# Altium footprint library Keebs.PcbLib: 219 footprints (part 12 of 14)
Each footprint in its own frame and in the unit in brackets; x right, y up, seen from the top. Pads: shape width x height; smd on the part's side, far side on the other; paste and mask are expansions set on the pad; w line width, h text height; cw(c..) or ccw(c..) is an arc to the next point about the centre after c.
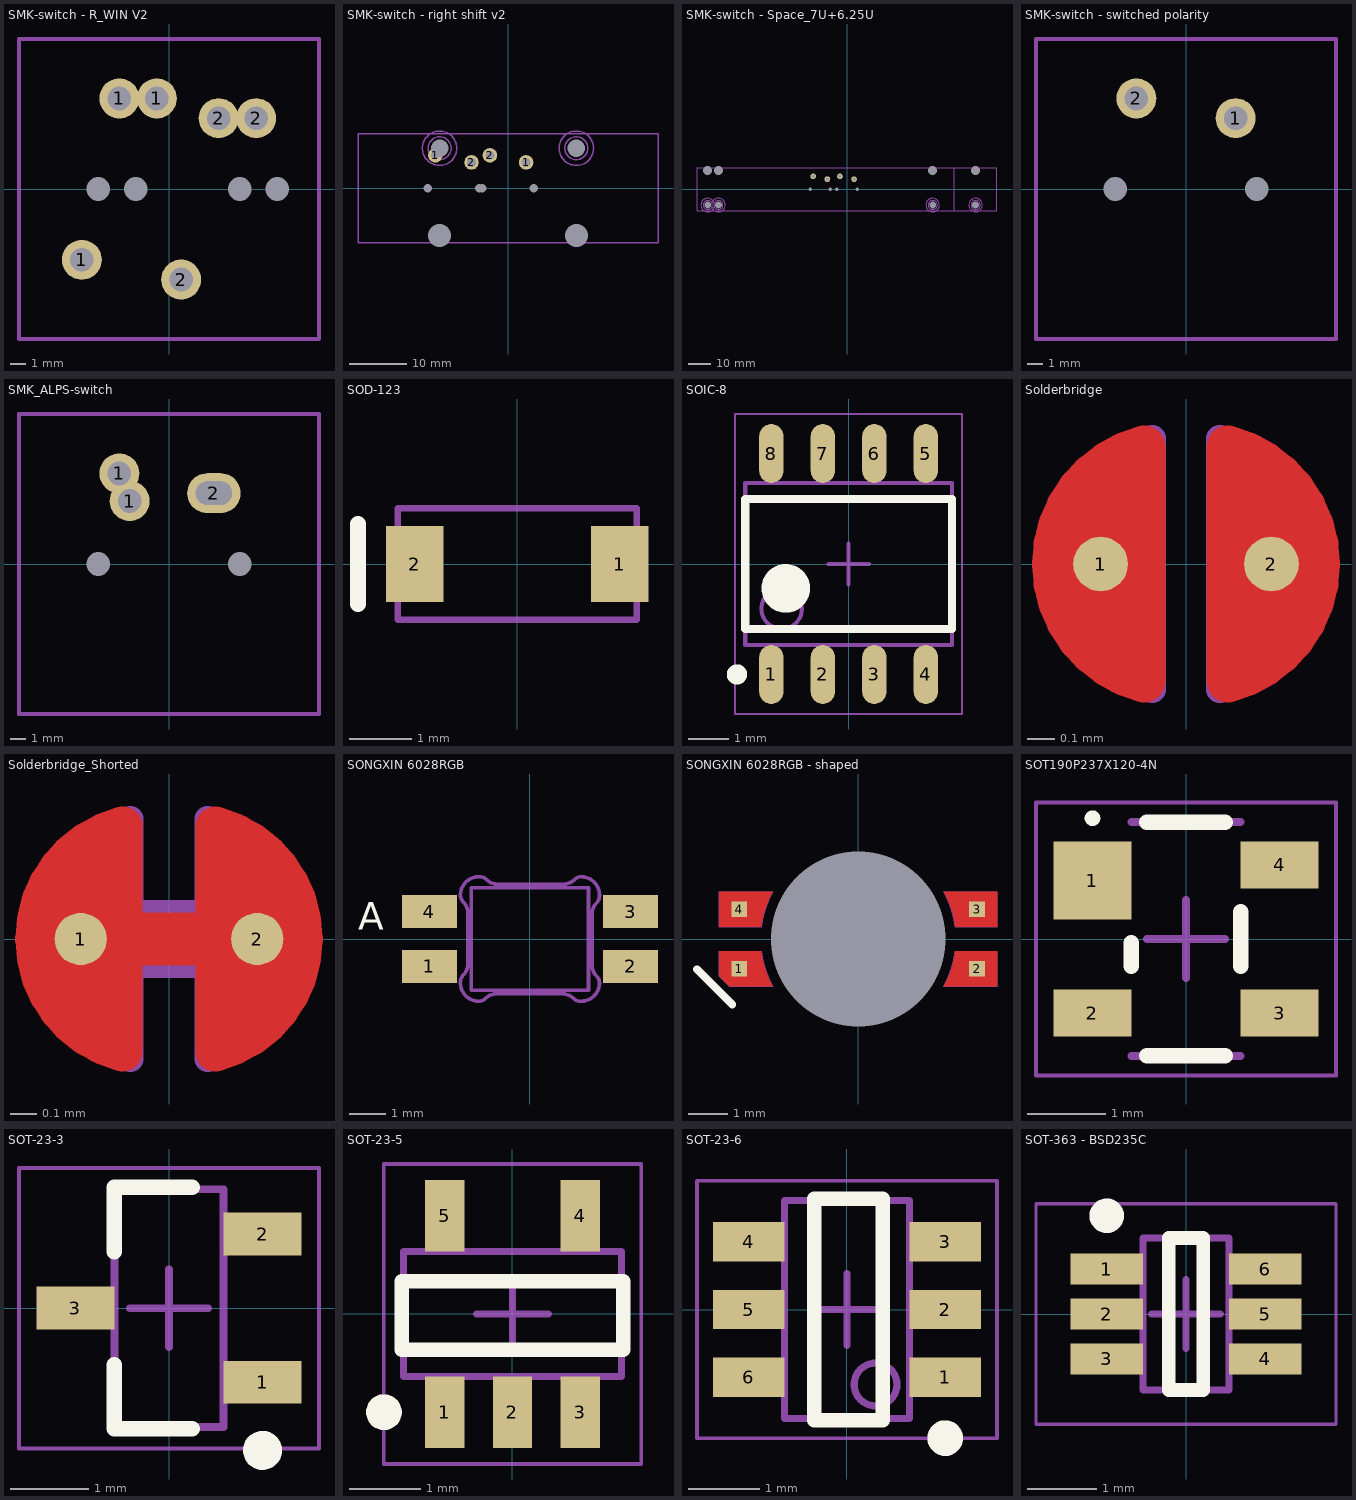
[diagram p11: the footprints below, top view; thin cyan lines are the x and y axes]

## SMK-switch - R_WIN V2 [mm] "Common tsangan and WK bottom + AEK"
pads (13):
  round 2.54 hole 1.5 mask-0.5: 1(-5.531,-4.5) 1(-3.15,5.75) 1(-0.769,5.75) 2(0.769,-5.75) 2(3.15,4.5) 2(5.531,4.5)
  round 1 hole 1.5 unplated: ""(-4.5,0) ""(-2.119,0) ""(4.5,0) ""(6.881,0)
  round 1 on Mech13: ""(-2.381,0) ""(0,0) ""(2.381,0)
Mechanical 13:
  lines w0.254: -9.525,-9.525 -9.525,9.525 9.525,9.525 9.525,-9.525 -9.525,-9.525
  text ".Designator" at -4.225,-8.325 h0.7

## SMK-switch - right shift v2 [mm]
pads (14):
  round 2.54 hole 1.5 mask-0.5: 1(-12.675,5.75) 1(3.15,4.5) 2(-6.375,4.5) 2(-3.15,5.75)
  round 1 hole 1.5 unplated: ""(-14.025,0) ""(-5.025,0) ""(-4.5,0) ""(4.5,0)
  round 1.524 hole 4 unplated: ""(-11.938,-8.255) ""(11.938,-8.255)
  round 1.524 hole 3.048 unplated: ""(-11.938,6.985) ""(11.938,6.985)
  round 1 on Mech13: ""(-9.525,0) ""(0,0)
Mechanical 13:
  lines w0.254: -26.194,-9.525 -26.194,9.525 26.194,9.525 26.194,-9.525 -26.194,-9.525
  text ".Designator" at -4.3,-5.55 h0.7
Mechanical 15:
  circle w0.254: c11.938,6.985 r2
  circle w0.254: c11.938,6.985 r3
  circle w0.254: c-11.938,6.985 r2
  circle w0.254: c-11.938,6.985 r3

## SMK-switch - Space_7U+6.25U [mm]
pads (18):
  round 2.54 hole 1.5 mask-0.5: 1(-8.756,4.5) 1(-3.15,5.75) 2(-15.056,5.75) 2(3.15,4.5)
  round 1.524 hole 3.048 unplated: ""(-61.91,-6.985) ""(-57.15,-6.985) ""(38.09,-6.985) ""(57.15,-6.985)
  round 1.524 hole 4 unplated: ""(-61.91,8.255) ""(-57.15,8.255) ""(38.09,8.255) ""(57.15,8.255)
  round 1 hole 1.5 unplated: ""(-16.406,0) ""(-7.406,0) ""(-4.5,0) ""(4.5,0)
  round 1 on Mech13: ""(-11.906,0) ""(0,0)
Mechanical 13:
  lines w0.254: 47.621,-9.525 47.621,9.525 ; -66.675,-9.525 -66.675,9.525 66.675,9.525 66.675,-9.525 -66.675,-9.525
  text ".Designator" at 7.625,-2.4 h0.7
Mechanical 15:
  circle w0.254: c57.15,-6.985 r3
  circle w0.254: c57.15,-6.985 r2
  circle w0.254: c38.09,-6.985 r3
  circle w0.254: c38.09,-6.985 r2
  circle w0.254: c-57.15,-6.985 r3
  circle w0.254: c-57.15,-6.985 r2
  circle w0.254: c-61.91,-6.985 r3
  circle w0.254: c-61.91,-6.985 r2
  text "7U" at 65.831,-1.85 h1.52
  text "6.25U" at 46.265,-3.6 h1.52

## SMK-switch - switched polarity [mm]
pads (5):
  round 2.54 hole 1.5 mask-0.5: 1(3.15,4.5) 2(-3.15,5.75)
  round 1 hole 1.5 unplated: ""(-4.5,0) ""(4.5,0)
  round 1 on Mech13: ""(0,0)
Mechanical 13:
  lines w0.254: -9.525,-9.525 9.525,-9.525 9.525,9.525 -9.525,9.525 -9.525,-9.525
  text ".Designator" at -3.575,-3.7 h0.7

## SMK_ALPS-switch [mm]
pads (6):
  round 2.54 hole 1.5 mask-0.5: 1(-3.15,5.75) 1(-2.5,4)
  oval 3.4x2.54 hole 1.5 slot 2.3 at 0 deg mask-1: 2(2.85,4.5)
  round 1 hole 1.5 unplated: ""(-4.5,0) ""(4.5,0)
  round 1 on Mech13: ""(0,0)
Mechanical 13:
  lines w0.254: -9.525,-9.525 9.525,-9.525 9.525,9.525 -9.525,9.525 -9.525,-9.525
  text ".Designator" at -3.575,-3.7 h0.7

## SOD-123 [mm]
pads (2):
  rect 0.91x1.22 smd: 1(1.635,0) 2(-1.635,0)
Top Overlay:
  lines w0.254: -2.54,-0.635 -2.54,0.635
Mechanical 13:
  lines w0.1: -1.905,-0.889 -1.905,0.889 1.905,0.889 1.905,-0.889 -1.905,-0.889
  text ".Designator" at -1.524,-0.127 h0.35
3D body "sod123 v4.step": height 1.2, standoff 0, extent -1.875,-0.85 1.875,0.85

## SOIC-8 [mm] "Based on AT24C256C datasheet"
height 1.75
pads (8):
  oval 0.6x1.45 smd: 1(-1.905,-2.725) 2(-0.635,-2.725) 3(0.635,-2.725) 4(1.905,-2.725) 5(1.905,2.725) 6(0.635,2.725) 7(-0.635,2.725) 8(-1.905,2.725)
Top Overlay:
  circle w0.6: c-1.55,-0.6 r0.3
  circle w0.25: c-2.755,-2.725 r0.125
  lines w0.2: -2.55,-1.6 -2.55,1.6 2.55,1.6 2.55,-1.6 -2.55,-1.6
Mechanical 13:
  circle w0.1: c-1.65,-1.1 r0.5
  lines w0.1: -2.55,-2 -2.55,2 2.55,2 2.55,-2 -2.55,-2
  text ".Designator" at -1.879,0.233 h0.45
Mechanical 15:
  lines w0.05: -2.8,-3.7 -2.8,3.7 2.8,3.7 2.8,-3.7 -2.8,-3.7
  lines w0.1: -0.5,0 0.5,0 ; 0,-0.5 0,0.5
3D body "SOIC-8.step": height 1.75, standoff 0, extent -2.55,-2.997 2.55,2.997

## Solderbridge [mm]
pads (2):
  round 0.2 smd paste-10: 1(-0.312,0) 2(0.312,0)
Top Layer:
  region: -0.077,-0.432 -0.152,-0.505 -0.271,-0.467 -0.335,-0.424 -0.409,-0.351 -0.462,-0.292 -0.521,-0.193 -0.549,-0.099 -0.544,0.122 -0.518,0.193 -0.434,0.33 -0.351,0.411 -0.259,0.469 -0.157,0.5 -0.107,0.483 -0.077,0.43
  region: 0.077,0.432 0.152,0.505 0.271,0.467 0.335,0.424 0.409,0.351 0.462,0.292 0.521,0.193 0.549,0.099 0.544,-0.122 0.518,-0.193 0.434,-0.33 0.351,-0.411 0.259,-0.469 0.157,-0.5 0.107,-0.483 0.077,-0.43
  lines w0.152: -0.153,-0.431 cw(c-0.042,0) -0.487,0 cw(c-0.042,0) -0.153,0.431 ; 0.153,-0.431 ccw(c0.042,0) 0.153,0.431
Top Solder:
  circle w0.61: c-0.003,0 r0.279
Mechanical 7:
  lines w0.1: -0.123,-0.459 cw(c-0.042,0) -0.123,0.459 -0.123,-0.459 ; 0.123,-0.459 ccw(c0.042,0) 0.123,0.459 0.123,-0.459
  text ".Designator" at 0.635,-0.152 h0.3

## Solderbridge_Shorted [mm]
pads (2):
  round 0.2 smd paste-10: 1(-0.338,0) 2(0.338,0)
Top Layer:
  region: 0.102,0.432 0.178,0.505 0.296,0.467 0.361,0.424 0.434,0.351 0.488,0.292 0.546,0.193 0.574,0.099 0.569,-0.122 0.544,-0.193 0.46,-0.33 0.376,-0.411 0.284,-0.469 0.183,-0.5 0.132,-0.483 0.102,-0.43
  region: -0.102,-0.432 -0.178,-0.505 -0.296,-0.467 -0.361,-0.424 -0.434,-0.351 -0.488,-0.292 -0.546,-0.193 -0.574,-0.099 -0.569,0.122 -0.544,0.193 -0.46,0.33 -0.376,0.411 -0.284,0.469 -0.183,0.5 -0.132,0.483 -0.102,0.43
  lines w0.152: -0.178,-0.431 cw(c-0.068,0) -0.178,0.431 ; 0.178,-0.431 ccw(c0.068,0) 0.178,0.431
  lines w0.203: -0.338,0 0.338,0
Top Solder:
  circle w0.61: c-0.028,0 r0.279
  circle w0.61: c0.028,0 r0.279
Mechanical 7:
  lines w0.1: -0.148,-0.459 cw(c-0.067,0) -0.148,0.459 -0.148,0.1 0.148,0.1 0.148,0.459 cw(c0.067,0) 0.148,-0.459 0.148,-0.1 -0.148,-0.1 -0.148,-0.459
  text ".Designator" at 0.635,-0.152 h0.3

## SONGXIN 6028RGB [mm] "Common Anode reverse mount LED"
pads (4):
  rect 1.5x0.9 smd: 1(-2.75,-0.75) 2(2.75,-0.75) 3(2.75,0.75) 4(-2.75,0.75)
Top Overlay:
  text "A" at -4.699,0.254 h0.75
Mechanical 1:
  lines w0.1: -1.9,-1.2 ccw(c-1.4,-1.2) -1.4,-1.7 ccw(c-1.4,-1.446) -1.22,-1.626 cw(c-0.914,-1.932) -0.914,-1.499 0.887,-1.499 cw(c0.887,-1.932) 1.194,-1.626 ccw(c1.373,-1.446) 1.373,-1.7 ; -1.9,-1.173 cw(c-1.646,-1.173) -1.826,-0.994 ccw(c-2.132,-0.687) -1.699,-0.687 -1.699,0.714 ccw(c-2.132,0.714) -1.826,1.02 cw(c-1.646,1.2) -1.9,1.2 cw(c-1.4,1.2) -1.4,1.7 -1.373,1.7 cw(c-1.373,1.446) -1.194,1.626 ccw(c-0.887,1.932) -0.887,1.499 0.914,1.499 ccw(c0.914,1.932) 1.22,1.626 cw(c1.4,1.446) 1.4,1.7 cw(c1.4,1.2) 1.9,1.2 ; 1.4,-1.7 ccw(c1.4,-1.2) 1.9,-1.2 ccw(c1.646,-1.2) 1.826,-1.02 cw(c2.132,-0.714) 1.699,-0.714 1.699,0.687 cw(c2.132,0.687) 1.826,0.994 ccw(c1.646,1.173) 1.9,1.173
Mechanical 13:
  lines w0.1: -1.6,-1.4 -1.6,1.4 ; -1.6,-1.4 1.6,-1.4 ; -1.6,-1.4 -1.6,1.4 ; -1.6,-1.4 1.6,-1.4 ; -1.6,1.4 1.6,1.4 ; -1.6,1.4 1.6,1.4 ; 1.6,-1.4 1.6,1.4 ; 1.6,-1.4 1.6,1.4
  text ".Designator" at -1.27,-0.127 h0.35
3D body "LED_SK6812MINI-E.step": height 0.94, standoff -0.84, extent -2.94,-1.403 2.94,1.397

## SONGXIN 6028RGB - shaped [mm] "Common Anode reverse mount LED"
pads (5):
  rect 0.4x0.4 smd: 1(-3,-0.75) 2(3,-0.75) 3(3,0.75) 4(-3,0.75)
  round 1 hole 4.4 unplated: ""(0,0)
Top Layer:
  region: -3.25,-1.195 -3.5,-0.945 -3.5,-0.304 -2.449,-0.304 -2.447,-0.304 -2.43,-0.421 -2.378,-0.651 -2.305,-0.875 -2.211,-1.091 -2.157,-1.195
  region: 2.157,-1.195 3.5,-1.195 3.5,-0.304 2.449,-0.304 2.447,-0.304 2.43,-0.421 2.378,-0.651 2.305,-0.875 2.211,-1.091
  region: 2.447,0.304 2.43,0.421 2.378,0.651 2.305,0.875 2.211,1.091 2.157,1.195 3.5,1.195 3.5,0.304
  region: -3.5,0.304 -3.5,1.195 -2.157,1.195 -2.211,1.091 -2.305,0.875 -2.378,0.651 -2.43,0.421 -2.447,0.304 -2.449,0.304
Top Overlay:
  lines w0.2: -4.064,-0.762 -3.175,-1.651
Mechanical 7:
  lines w0.01: -2.449,-0.304 -3.455,-0.304 -3.5,-0.304 -3.5,-0.945 -3.25,-1.195 -2.211,-1.195 -2.157,-1.195 cw(c0,0) -2.447,-0.304 ; -2.449,0.304 -3.455,0.304 -3.5,0.304 -3.5,0.349 -3.5,1.154 -3.5,1.195 -3.476,1.195 -2.211,1.195 -2.157,1.195 ccw(c0,0) -2.447,0.304 ; 2.447,-0.304 cw(c0,0) 2.157,-1.195 2.211,-1.195 3.476,-1.195 3.5,-1.195 3.5,-1.154 3.5,-0.349 3.5,-0.304 3.455,-0.304 2.449,-0.304 ; 2.447,0.304 ccw(c0,0) 2.157,1.195 2.211,1.195 3.476,1.195 3.5,1.195 3.5,1.154 3.5,0.349 3.5,0.304 3.455,0.304 2.449,0.304
Mechanical 13:
  lines w0.1: -1.6,-1.4 1.6,-1.4 1.6,1.4 -1.6,1.4 -1.6,-1.4
  text ".Designator" at -1.27,-0.127 h0.35
3D body "LED_SK6812MINI-E.step": height 0.94, standoff -0.84, extent -2.94,-1.403 2.94,1.397

## SOT190P237X120-4N [mm] "SOT143, 4-Leads, Body 3,00x2,37mm, Pitch 1,90mm, IPC Medium Density"
height 1.2
pads (4):
  rect 1x1 smd: 1(-1.2,0.75)
  rect 1x0.6 smd: 2(-1.2,-0.95) 3(1.2,-0.95) 4(1.2,0.95)
Top Overlay:
  circle w0.1: c-1.2,1.55 r0.05
  lines w0.2: -0.7,-0.35 -0.7,-0.05 ; -0.5,-1.5 0.5,-1.5 ; -0.5,1.5 0.5,1.5 ; 0.7,-0.35 0.7,0.35
Mechanical 13:
  lines w0.1: -0.7,-1.5 0.7,-1.5 ; -0.7,1.5 0.7,1.5
  text ".Designator" at 0.1,-1.325 h0.35
Mechanical 15:
  lines w0.05: -1.925,-1.75 -1.925,1.75 1.925,1.75 1.925,-1.75 -1.925,-1.75
  lines w0.1: -0.5,0 0.5,0 ; 0,-0.5 0,0.5
3D body "SOT143B.step": height 1.09, standoff 0, extent -1.245,-1.499 1.245,1.499

## SOT-23-3 [mm] "3.3v regulator, used in Windsond S2 proto 1"
height 1.12
pads (3):
  rect 1x0.55 smd: 1(1.2,-0.95) 2(1.2,0.95) 3(-1.2,0)
Top Overlay:
  circle w0.25: c1.2,-1.825 r0.125
  lines w0.2: -0.7,-0.725 -0.7,-1.55 0.3,-1.55 ; -0.7,0.725 -0.7,1.55 0.3,1.55
Mechanical 13:
  lines w0.1: -0.7,-1.525 0.7,-1.525 0.7,1.525 -0.7,1.525 -0.7,-1.525
  text ".Designator" at 0.275,-1.625 h0.45
Mechanical 15:
  lines w0.05: -1.925,-1.8 1.925,-1.8 1.925,1.8 -1.925,1.8 -1.925,-1.8
  lines w0.1: -0.5,0 0.5,0 ; 0,-0.5 0,0.5
3D body "SOT-23.stp": height 1, standoff 0, extent -1.102,-1.5 1.448,1.5

## SOT-23-5 [mm]
height 1.45
pads (5):
  rect 0.55x1 smd: 1(-0.95,-1.375) 2(0,-1.375) 3(0.95,-1.375) 4(0.95,1.375) 5(-0.95,1.375)
Top Overlay:
  circle w0.25: c-1.8,-1.375 r0.125
  lines w0.2: -1.55,-0.5 -1.55,0.457 1.55,0.457 1.55,-0.5 -1.55,-0.5
Mechanical 13:
  lines w0.1: -1.525,-0.875 1.525,-0.875 1.525,0.875 -1.525,0.875 -1.525,-0.875
  text ".Designator" at 1.525,0.2 h0.45
Mechanical 15:
  lines w0.05: -1.8,-2.1 1.8,-2.1 1.8,2.1 -1.8,2.1 -1.8,-2.1
  lines w0.1: 0,-0.5 0,0.5 ; -0.5,0 0.5,0 -0.5,0
3D body "SOT23_5.stp": height 0.92, standoff 0.01, extent -1.5,-1.6 1.5,1.604

## SOT-23-6 [mm]
height 1.45
pads (6):
  rect 1x0.55 smd: 1(1.375,-0.95) 2(1.375,0) 3(1.375,0.95) 4(-1.375,0.95) 5(-1.375,0) 6(-1.375,-0.95)
Top Overlay:
  circle w0.25: c1.375,-1.8 r0.125
  lines w0.2: -0.457,-1.55 0.5,-1.55 0.5,1.55 -0.457,1.55 -0.457,-1.55
Mechanical 13:
  circle w0.1: c0.4,-1.05 r0.3
  lines w0.1: -0.875,-1.525 -0.875,1.525 0.875,1.525 0.875,-1.525 -0.875,-1.525
  text ".Designator" at -0.33,1.473 h0.45
Mechanical 15:
  lines w0.05: -2.1,-1.8 -2.1,1.8 2.1,1.8 2.1,-1.8 -2.1,-1.8
  lines w0.1: -0.5,0 0.5,0 ; 0,-0.5 0,0.5
3D body "sot-23-6.stp": height 1.05, standoff -0.06, extent -1.472,-1.485 1.373,1.436

## SOT-363 - BSD235C [mm] "SOT23, 6-Leads, Body 2,00x2,10mm, Pitch 0,65mm, IPC Low Density"
height 0.9
pads (6):
  rect 1.05x0.45 smd: 1(-1.15,0.65) 2(-1.15,0) 3(-1.15,-0.65) 4(1.15,-0.65) 5(1.15,0) 6(1.15,0.65)
Top Overlay:
  circle w0.25: c-1.15,1.425 r0.125
  lines w0.2: -0.25,-1.1 0.25,-1.1 0.25,1.1 -0.25,1.1 -0.25,-1.1
Mechanical 13:
  lines w0.1: -0.625,-1.1 -0.625,1.1 0.625,1.1 0.625,-1.1 -0.625,-1.1
  text ".Designator" at -0.225,0.925 h0.35
Mechanical 15:
  lines w0.05: -2.175,-1.6 -2.175,1.6 2.175,1.6 2.175,-1.6 -2.175,-1.6
  lines w0.1: -0.5,0 0.5,0 ; 0,-0.5 0,0.5
3D body "SOT-363 - BSD235C.step": height 0.9, standoff 0, extent -1.2,-1.1 1.2,1.1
